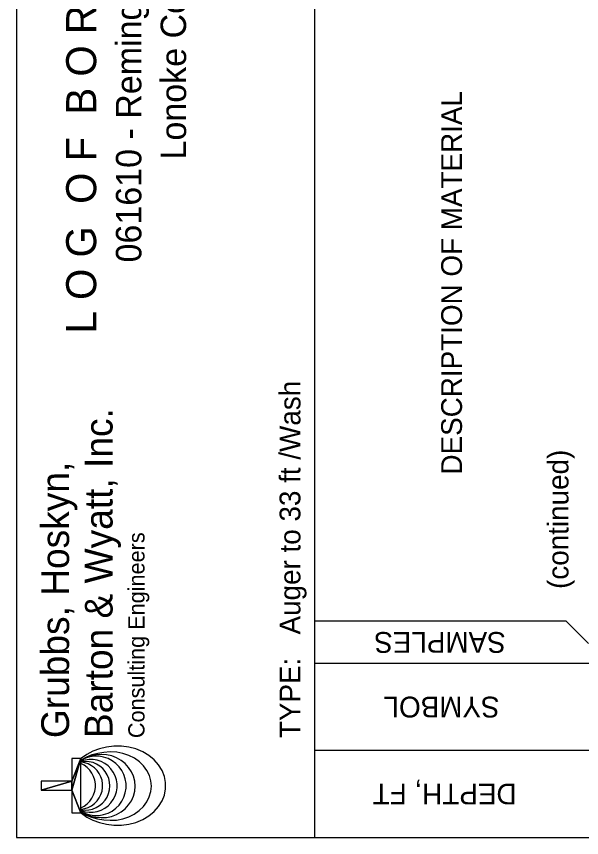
# Model space of a CAD drawing. Extents: x 1313964 to 1316843, y 2087046 to 2096619.
# Drawn here: x 1314075.31 to 1314089.13, y 2089873.43 to 2089893.52 of the extents above; entities that cross this region are included whole.
import ezdxf

# ---------------------------------------------------------------- set-up
doc = ezdxf.new("R2010")
doc.units = 0
doc.layers.add('B-Sub-Contour', color=7, linetype='Continuous')
doc.layers.add('Default', color=7, linetype='Continuous')

# ---------------------------------------------------------------- blocks, each defined once
blk = doc.blocks.new('DGRFC_GGHLOGO')
at = {"layer": 'Default'}
for points in [[(371581.68, 791230.32), (371581.68, 1050310.32), (295381.68, 1050310.32), (371581.68, 791230.32)], [(371581.68, 791230.32), (295381.68, 1050310.32), (295381.68, 791230.32), (371581.68, 791230.32)], [(295381.68, 791230.32), (104881.68, 791230.32), (104881.68, 715030.32), (295381.68, 791230.32)], [(295381.68, 791230.32), (104881.68, 715030.32), (562081.68, 715030.32), (295381.68, 791230.32)], [(295381.68, 791230.32), (562081.68, 715030.32), (371581.68, 791230.32), (295381.68, 791230.32)], [(562081.68, 715030.32), (562081.68, 791230.32), (371581.68, 791230.32), (562081.68, 715030.32)]]:
    blk.add_lwpolyline(points, close=True, dxfattribs=at)
for points in [[(105216.96, 715030.32), (100004.88, 709757.28), (68915.28, 666170.88), (42854.88, 615848.4), (22494.24, 560009.04), (8351.52, 500115.84), (792.48, 437662.32), (0, 374202.96), (7802.88, 311353.2), (23439.12, 250698), (46847.76, 193791.84), (77510.64, 142006.32), (114635.28, 96713.04), (157246.32, 59039.76), (204337.92, 29900.88), (254660.4, 10058.4), (306994.56, 0), (359968.8, 0), (412302.96, 10058.4), (462625.44, 29900.88), (509717.04, 59039.76), (552328.08, 96713.04), (589452.72, 142006.32), (620115.6, 193791.84), (643524.24, 250698), (659160.48, 311353.2), (666963.36, 374202.96), (666170.88, 437662.32), (658611.84, 500115.84), (644469.12, 560009.04), (624108.48, 615848.4), (598048.08, 666170.88), (566958.48, 709757.28), (561746.4, 715030.32)], [(111587.28, 715030.32), (108691.68, 711311.76), (85770.72, 670895.28), (67177.92, 625266.72), (53400.96, 575584.32), (44744.64, 523097.76), (41422.32, 469087.2), (42702.48, 414924.24), (52760.88, 362010.96), (69738.24, 311597.04), (93238.32, 264993.12), (122651.52, 223387.92), (157246.32, 187756.8), (196169.28, 159075.12), (238414.56, 137982.96), (282976.32, 125089.92), (328665.84, 120639.84), (374385.84, 124815.6), (419008.56, 137464.8), (461345.28, 158282.64), (500390.16, 186720.48), (535137.36, 222138.24), (564733.44, 263591.04), (588416.4, 310042.56), (605637.6, 360334.56), (615909.36, 413217.36), (618195.36, 467349.84), (615055.92, 521360.4), (606582.48, 573938.4), (592927.44, 623742.72), (574487.04, 669523.68), (551718.48, 710123.04), (547908.48, 715030.32)], [(113477.04, 715030.32), (111434.88, 712226.16), (91531.44, 674613.84), (76748.64, 633618.24), (67421.76, 590275.68), (63825.12, 545683.44), (65227.2, 500969.28), (74462.64, 457260.96), (90098.88, 415625.28), (111770.16, 377098.56), (138927.84, 342717.12), (170870.88, 313273.44), (206837.28, 289560), (245882.16, 272155.92), (287030.16, 261457.44), (329031.6, 257799.84), (371520.72, 261244.08), (412729.68, 271698.72), (451866, 288889.44), (487923.84, 312420), (520019.28, 341680.8), (547329.36, 375940.32), (569183.52, 414314.64), (585033.12, 455889.36), (594451.44, 499567.2), (596463.12, 544250.88), (593049.36, 588873.6), (583905.36, 632246.64), (569305.44, 673333.68), (549554.4, 711067.92), (546658.8, 715030.32)], [(117957.6, 715030.32), (116220.24, 712561.44), (98968.56, 677509.44), (87386.16, 640201.92), (81747.36, 601522.8), (82174.08, 562477.92), (88696.8, 523951.2), (101071.68, 486887.52), (119085.36, 452231.76), (142250.16, 420776.4), (170047.92, 393283.44), (201747.12, 370453.92), (236616.24, 352836.48), (273801.84, 340857.84), (312389.52, 334792.32), (351464.88, 334792.32), (390052.56, 340857.84), (427238.16, 352836.48), (462107.28, 370453.92), (493806.48, 393283.44), (521573.76, 420776.4), (544769.04, 452231.76), (562752.24, 486887.52), (575157.6, 523951.2), (581649.84, 562477.92), (582076.56, 601522.8), (576437.76, 640201.92), (564855.36, 677509.44), (547634.16, 712561.44), (545896.8, 715030.32)], [(124632.72, 715030.32), (123809.76, 713353.92), (113934.24, 680252.64), (109301.28, 646023.6), (110002.32, 611459.28), (116006.88, 577443.6), (127223.52, 544769.04), (143316.96, 514228.08), (163982.4, 486521.76), (188640.72, 462351.12), (216743.28, 442264.8), (247619.52, 426780.96), (280507.44, 416234.88), (314645.04, 410900.88), (349209.36, 410900.88), (383316.48, 416234.88), (416234.88, 426780.96), (447080.64, 442264.8), (475213.68, 462351.12), (499872, 486521.76), (520506.96, 514228.08), (536630.88, 544769.04), (547847.52, 577443.6), (553852.08, 611459.28), (554553.12, 646023.6), (549920.16, 680252.64), (540014.16, 713353.92), (539221.68, 715030.32)], [(130972.56, 715030.32), (130454.4, 713079.6), (127284.48, 680740.32), (129235.2, 648309.6), (136306.56, 616579.92), (148254.72, 586343.76), (164805.36, 558393.6), (185562.24, 533400), (210007.2, 511972.56), (237530.64, 494659.92), (267401.04, 481919.28), (298917.36, 474024.96), (331317.6, 471190.32), (363717.84, 473506.8), (395356.08, 480882.96), (425470.32, 493166.4), (453237.6, 510021.84), (478017.84, 531053.04), (499170.96, 555711.36), (516178.8, 583417.68), (528614.64, 613440.48), (536173.68, 645048.24), (538642.56, 677448.48), (535990.8, 709818.24), (534710.64, 715030.32)], [(135483.6, 715030.32), (135483.6, 714420.72), (140482.32, 683727.36), (150174.96, 654192.24), (164378.64, 626546.88), (182727.6, 601431.36), (204764.64, 579485.76), (229941.12, 561258.72), (257647.44, 547176.96), (287243.52, 537606.24), (317936.88, 532759.92), (349026.48, 532759.92), (379719.84, 537606.24), (409315.92, 547176.96), (437022.24, 561258.72), (462198.72, 579485.76), (484235.76, 601431.36), (502584.72, 626546.88), (516788.4, 654192.24), (526481.04, 683727.36), (531479.76, 714420.72), (531479.76, 715030.32)], [(146151.6, 715030.32), (160690.56, 687811.68), (179679.6, 662574.24), (202326.24, 640567.68), (228112.32, 622279.68), (256367.28, 608167.44), (286481.52, 598566.24), (317693.04, 593719.92), (349270.32, 593719.92), (380481.84, 598566.24), (410596.08, 608167.44), (438851.04, 622279.68), (464637.12, 640567.68), (487283.76, 662574.24), (506272.8, 687811.68), (520811.76, 715030.32)]]:
    blk.add_lwpolyline(points, dxfattribs=at)

msp = doc.modelspace()

# ---------------------------------------------------------------- linework, layer by layer
at = {"layer": 'B-Sub-Contour'}
for points in [[(1314136.725, 2089873.434), (1314136.725, 2089916.306), (1314075.306, 2089916.306), (1314075.306, 2089873.434), (1314136.725, 2089873.434)], [(1314082.603, 2089873.434), (1314082.603, 2089916.306)], [(1314088.745, 2089878.725), (1314082.603, 2089878.725)], [(1314089.292, 2089878.178), (1314088.745, 2089878.725)], [(1314134.292, 2089877.691), (1314082.603, 2089877.691)], [(1314134.292, 2089875.563), (1314082.603, 2089875.563)]]:
    msp.add_lwpolyline(points, dxfattribs=at)

# ---------------------------------------------------------------- block references
at = {"layer": 'B-Sub-Contour', "xscale": 2.894891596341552e-06, "yscale": 2.894891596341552e-06, "rotation": 90}
msp.add_blockref('DGRFC_GGHLOGO', (1314078.955, 2089873.738), dxfattribs=at)

# ---------------------------------------------------------------- texts
at = {"layer": 'B-Sub-Contour'}
for s, height, rotation, p in [('L O G  O F  B O R I N G  N O.  S2', 0.7352, 90, (1314077.257, 2089885.763)), ('061610 - Remington Road over I-40', 0.62209, 90, (1314078.361, 2089887.499)), ('Lonoke County, Arkansas', 0.62209, 90, (1314079.455, 2089890.018)), ('DESCRIPTION OF MATERIAL', 0.50899, 90, (1314086.202, 2089882.313)), ('TYPE:   Auger to 33 ft /Wash', 0.50899, 90, (1314082.25, 2089875.867)), ('Barton & Wyatt, Inc.', 0.67865, 90, (1314077.657, 2089875.867)), ('(continued)', 0.50899, 90, (1314088.806, 2089879.515)), ('Grubbs, Hoskyn,', 0.67865, 90, (1314076.593, 2089875.867)), ('Consulting Engineers', 0.39588, 90, (1314078.438, 2089875.867)), ('SAMPLES', 0.509, 180, (1314087.271, 2089878.462)), ('SYMBOL', 0.509, 180, (1314087.12, 2089876.881)), ('DEPTH, FT', 0.509, 180, (1314087.536, 2089874.753))]:
    msp.add_text(s, height=height, rotation=rotation, dxfattribs=at).set_placement(p)

doc.saveas('drawing.dxf')
